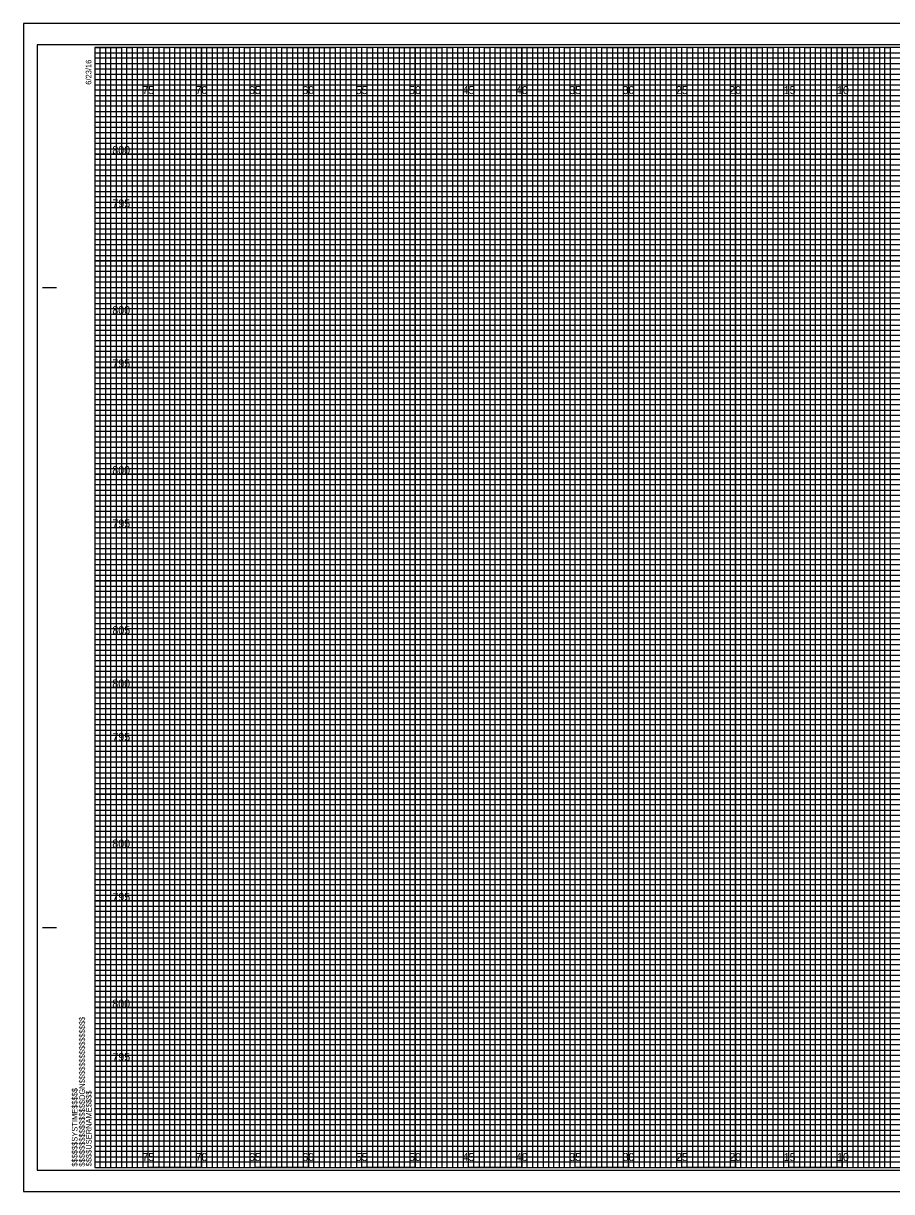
# Model space of a CAD drawing. Extents: x -7 to 162, y -2 to 107.
# Drawn here: x -6.7 to 74.6, y -2.3 to 107.3 of the extents above; entities that cross this region are included whole.
import ezdxf

# ---------------------------------------------------------------- set-up
doc = ezdxf.new("R2010")
doc.units = 0
for name, color, linetype in [('Exist Cross Section Cell', 7, 'Continuous'), ('Exist XS Center Line Elevation Label', 7, 'Continuous'), ('Prop CMT Pvmt Course 2 Wedge', 7, 'Continuous'), ('Prop CMT Shld Paved Course 3', 7, 'Continuous'), ('Prop XS Elevation Labels', 7, 'Continuous'), ('Prop XS Hydro Elevations', 7, 'Continuous'), ('Prop XS SE Text', 7, 'Continuous'), ('Prop XS Side Slope Text', 7, 'Continuous'), ('Sheet Cross Section Grid Minor 2 CELL', 7, 'Continuous'), ('Sheet DOT Grid CELL', 7, 'Continuous'), ('Sheet Plot Border Inside CELL', 7, 'Continuous')]:
    doc.layers.add(name, color=color, linetype=linetype)

msp = doc.modelspace()

# ---------------------------------------------------------------- linework, layer by layer
at = {"layer": 'Exist Cross Section Cell'}
for p, q in [((5, 105), (0, 105)), ((5, 0), (5, 105)), ((15, 105), (10, 105)), ((10, 105), (10, 0)), ((15, 0), (15, 105)), ((25, 105), (20, 105)), ((20, 105), (20, 0)), ((25, 0), (25, 105)), ((35, 105), (30, 105)), ((30, 105), (30, 0)), ((35, 0), (35, 105)), ((45, 105), (40, 105)), ((40, 105), (40, 0)), ((45, 0), (45, 105)), ((55, 105), (50, 105)), ((50, 105), (50, 0)), ((55, 0), (55, 105)), ((65, 105), (60, 105)), ((60, 105), (60, 0)), ((65, 0), (65, 105)), ((75, 105), (70, 105)), ((70, 105), (70, 0)), ((10, 0), (5, 0)), ((20, 0), (15, 0)), ((30, 0), (25, 0)), ((40, 0), (35, 0)), ((50, 0), (45, 0)), ((60, 0), (55, 0)), ((70, 0), (65, 0))]:
    msp.add_line(p, q, dxfattribs=at)
for points in [[(0, 100), (160, 100), (160, 95), (0, 95)], [(0, 90), (160, 90), (160, 85), (0, 85)], [(0, 80), (160, 80), (160, 75), (0, 75)], [(0, 70), (160, 70), (160, 65), (0, 65)], [(0, 60), (160, 60), (160, 55), (0, 55)], [(0, 50), (160, 50), (160, 45), (0, 45)], [(0, 40), (160, 40), (160, 35), (0, 35)], [(0, 30), (160, 30), (160, 25), (0, 25)], [(0, 20), (160, 20), (160, 15), (0, 15)], [(0, 10), (160, 10), (160, 5), (0, 5)]]:
    msp.add_lwpolyline(points, dxfattribs=at)
at = {"layer": 'Exist XS Center Line Elevation Label'}
for points in [[(0, 105), (2.5, 105), (2.5, 0), (7.5, 0), (7.5, 105), (12.5, 105), (12.5, 0), (17.5, 0), (17.5, 105), (22.5, 105), (22.5, 0), (27.5, 0), (27.5, 105), (32.5, 105), (32.5, 0), (37.5, 0), (37.5, 105), (42.5, 105), (42.5, 0), (47.5, 0), (47.5, 105), (52.5, 105), (52.5, 0), (57.5, 0), (57.5, 105), (62.5, 105), (62.5, 0), (67.5, 0), (67.5, 105), (72.5, 105), (72.5, 0), (77.5, 0)], [(0, 102.5), (137.5, 102.5)], [(0, 92.5), (160, 92.5), (160, 97.5), (0, 97.5)], [(0, 82.5), (160, 82.5), (160, 87.5), (0, 87.5)], [(0, 72.5), (160, 72.5), (160, 77.5), (0, 77.5)], [(0, 62.5), (160, 62.5), (160, 67.5), (0, 67.5)], [(0, 52.5), (160, 52.5), (160, 57.5), (0, 57.5)], [(0, 42.5), (160, 42.5), (160, 47.5), (0, 47.5)], [(0, 32.5), (160, 32.5), (160, 37.5), (0, 37.5)], [(0, 22.5), (160, 22.5), (160, 27.5), (0, 27.5)], [(0, 12.5), (160, 12.5), (160, 17.5), (0, 17.5)], [(0, 2.5), (160, 2.5), (160, 7.5), (0, 7.5)]]:
    msp.add_lwpolyline(points, dxfattribs=at)
at = {"layer": 'Prop CMT Pvmt Course 2 Wedge'}
for p, q in [((161.65, 107.25), (-6.7, 107.25)), ((-6.7, 107.25), (-6.7, -2.25)), ((-6.7, -2.25), (161.65, -2.25))]:
    msp.add_line(p, q, dxfattribs=at)
at = {"layer": 'Prop CMT Shld Paved Course 3'}
msp.add_lwpolyline([(-6.7, -2.25), (161.65, -2.25), (161.65, 107.25), (-6.7, 107.25)], close=True, dxfattribs=at)
at = {"layer": 'Prop XS Hydro Elevations'}
for p, q in [((-4.9, 82.5), (-3.65, 82.5)), ((-4.85, 82.5), (-3.6, 82.5)), ((-4.9, 22.5), (-3.65, 22.5)), ((-4.85, 22.5), (-3.6, 22.5)), ((0, 0), (0, 0)), ((0, 0), (0, 0)), ((0, 0), (0, 0)), ((0, 0), (0, 0)), ((0, 0), (0, 0)), ((0, 0), (0, 0)), ((0, 0), (0, 0))]:
    msp.add_line(p, q, dxfattribs=at)
msp.add_lwpolyline([(160, 105), (0, 105), (0, 0), (160, 0)], close=True, dxfattribs=at)
at = {"layer": 'Prop XS Side Slope Text'}
for p, q in [((0, 104.5), (130, 104.5)), ((130, 103.99), (0, 103.99)), ((0, 103.99), (0, 103.5)), ((0, 103.5), (130, 103.5)), ((130, 102.95), (0, 102.95)), ((0, 102.95), (0, 102)), ((0, 102), (160, 102))]:
    msp.add_line(p, q, dxfattribs=at)
for points in [[(0, 101.5), (135, 101.5), (160, 101.5), (160, 101), (0, 101)], [(0, 100.5), (160, 100.5), (160, 99.5), (0, 99.5)], [(0, 99), (160, 99), (160, 98.5), (0, 98.49)], [(0, 98), (160, 98), (160, 97), (0, 97)], [(0, 96.5), (160, 96.5), (160, 96), (0, 96)], [(0, 95.5), (160, 95.5), (160, 94.5), (0, 94.5)], [(0, 94), (160, 94), (160, 93.5), (0, 93.5)], [(0, 93), (160, 93), (160, 92), (0, 92)], [(0, 91.5), (160, 91.5), (160, 91), (0, 91)], [(0, 90.5), (160, 90.5), (160, 89.5), (0, 89.5)], [(0, 89), (160, 89), (160, 88.5), (0, 88.5)], [(0, 88), (160, 88), (160, 86.98), (160, 86.5), (160, 86), (0, 86)], [(0, 87), (160, 87), (160, 86.5), (0, 86.5)], [(0, 85.5), (160, 85.5), (160, 84.5), (0, 84.52)], [(0, 84.52), (160, 84.5), (160, 84), (0, 84)], [(0, 83.5), (160, 83.5), (160, 83), (0, 83)], [(0, 82), (160, 82), (160, 81.5), (0, 81.5)], [(0, 81), (160, 81), (160, 80.5), (0, 80.5)], [(-0.04, 79.45), (160, 79.45), (160, 78.94), (-0.04, 78.94)], [(0, 78.5), (160, 78.5), (160, 78), (0, 78)], [(0, 77), (160, 77), (160, 76.5), (0, 76.5)], [(0, 76), (160, 76), (160, 75.5), (0, 75.5)], [(0, 74.5), (160, 74.5), (160, 74), (0, 74)], [(0, 73.5), (160, 73.5), (160, 73), (0, 73)], [(0, 72), (160, 72), (160, 71.5), (0, 71.5)], [(0, 71), (160, 71), (160, 70.5), (0, 70.5)], [(0, 69.5), (160, 69.5), (160, 68.99), (0, 69)], [(0, 68.5), (160, 68.5), (160, 68), (0, 68)], [(0, 67), (160, 67), (160, 66.5), (0, 66.5)], [(0, 66), (160, 66), (160, 65.5), (0, 65.5)], [(0, 64.5), (160, 64.5), (160, 64), (0, 64)], [(0, 63.5), (160, 63.5), (160, 63), (0, 63)], [(0, 62), (160, 62), (160, 61.5), (0, 61.5)], [(0, 61), (160, 61), (160, 60.5), (0, 60.5)], [(0, 59.5), (160, 59.5), (160, 59), (0, 59)], [(0, 58.5), (160.03, 58.45), (160, 58), (0, 58)], [(0, 57), (160, 57), (160, 56.5), (0, 56.5)], [(0, 56), (160, 56), (160, 55.5), (0, 55.5)], [(0, 54.5), (160, 54.5), (160, 54), (0, 54)], [(0, 53.5), (160, 53.5), (160, 53), (0, 53)], [(0, 52), (160, 52), (160, 51.5), (0, 51.5)], [(0, 51), (160, 51), (160, 50.5), (0, 50.5)], [(0, 49.5), (160, 49.5), (160, 49), (0, 49)], [(0, 48.5), (160, 48.5), (160, 48), (0, 48)], [(0, 47), (160, 47), (160, 46.5), (0, 46.5)], [(0, 46), (160, 46), (160, 45.5), (0, 45.5)], [(0, 44.5), (160, 44.5), (160, 44), (0, 44)], [(0, 43.5), (160, 43.5), (160, 43), (0, 43)], [(0, 42), (160, 42), (160, 41.5), (0, 41.5)], [(0, 41), (160, 41), (160, 40.5), (0, 40.5)], [(0, 39.5), (160, 39.5), (160, 38.99), (0, 39)], [(0, 38.5), (160, 38.5), (160, 38), (0, 38)], [(0, 37), (160, 37), (160, 36.5), (0, 36.5)], [(0, 36), (160, 36), (160, 35.5), (0, 35.5)], [(0, 34.5), (160, 34.5), (160, 34), (0, 34)], [(0, 33.5), (160, 33.5), (160, 33), (0, 33)], [(0, 32), (160, 32), (160, 31.5), (0, 31.5)], [(0, 31), (160, 31), (160, 30.5), (0, 30.5)], [(0, 29.5), (160, 29.5), (160, 29), (0, 29)], [(0, 28.5), (160.03, 28.46), (160, 28), (0, 28)], [(0, 27), (160, 27), (160, 26.5), (0, 26.5)], [(0, 26), (160, 26), (160, 25.5), (0, 25.5)], [(0, 24.5), (160, 24.5), (160, 24), (0, 24)], [(0, 23.5), (160, 23.5), (160, 23), (0, 23)], [(0, 22), (160, 22), (160, 21.5), (0, 21.5)], [(0, 21), (160, 21), (160, 20.5), (0, 20.5)], [(0, 19.5), (160, 19.5), (160, 19), (0, 19)], [(0, 18.5), (160, 18.5), (160, 18), (0, 18)], [(0, 17), (160, 17), (160, 16.5), (0, 16.5)], [(0, 16), (160, 16), (160, 15.5), (0, 15.5)], [(0, 14.5), (160, 14.5), (160, 14), (0, 14)], [(0, 13.5), (160, 13.5), (160, 13), (0, 13)], [(0, 12), (160, 12), (160, 11.5), (0, 11.5)], [(0, 11), (160, 11), (160, 10.5), (0, 10.5)], [(0, 9.5), (160, 9.5), (160, 9), (0, 9)], [(0, 8.5), (160, 8.5), (160, 8), (0, 8)], [(0, 7), (160, 7), (160, 6.5), (0, 6.5)], [(0, 6), (160, 6), (160, 5.5), (0, 5.5)], [(0, 4.5), (160, 4.5), (160, 4), (0, 4)], [(0, 3.5), (160, 3.5), (160, 3), (0, 3)], [(0, 2), (160, 2), (160, 1.5), (0, 1.5)], [(0, 1), (160, 1), (160, 0.5), (0, 0.5)]]:
    msp.add_lwpolyline(points, dxfattribs=at)
at = {"layer": 'Sheet Cross Section Grid Minor 2 CELL'}
for points in [[(0, 0), (0.5, 0), (0.5, 105), (1, 105), (1, 0)], [(1, 0), (1.5, 0), (1.5, 105), (2, 105), (2, 0)], [(2.5, 0), (3, 0), (3, 105), (3.5, 105), (3.5, 0)], [(3.5, 0), (4, 0), (4, 105), (4.5, 105), (4.5, 0)], [(5, 0), (5.5, 0), (5.5, 105), (6, 105), (6, 0)], [(6, 0), (6.5, 0), (6.5, 105), (7, 105), (7, 0)], [(7.5, 0), (8, 0), (8, 105), (8.5, 105), (8.5, 0)], [(8.5, 0), (9, 0), (9, 105), (9.5, 105), (9.5, 0)], [(10, 0), (10.5, 0), (10.5, 105), (11, 105), (11, 0)], [(11, 0), (11.5, 0), (11.5, 105), (12, 105), (12, 0)], [(12.5, 0), (13, 0), (13, 105), (13.5, 105), (13.5, 0)], [(13.5, 0), (14, 0), (14, 105), (14.5, 105), (14.5, 0)], [(15, 0), (15.5, 0), (15.5, 105), (16, 105), (16, 0)], [(16, 0), (16.5, 0), (16.5, 105), (17, 105), (17, 0)], [(17.5, 0), (18, 0), (18, 105), (18.5, 105), (18.5, 0)], [(18.5, 0), (19, 0), (19, 105), (19.5, 105), (19.5, 0)], [(20, 0), (20.5, 0), (20.5, 105), (21, 105), (21, 0)], [(21, 0), (21.5, 0), (21.5, 105), (22, 105), (22, 0)], [(22.5, 0), (23, 0), (23, 105), (23.5, 105), (23.5, 0)], [(23.5, 0), (24, 0), (24, 105), (24.5, 105), (24.5, 0)], [(25, 0), (25.5, 0), (25.5, 105), (26, 105), (26, 0)], [(26, 0), (26.5, 0), (26.5, 105), (27, 105), (27, 0)], [(27.5, 0), (28, 0), (28, 105), (28.5, 105), (28.5, 0)], [(28.5, 0), (29, 0), (29, 105), (29.5, 105), (29.5, 0)], [(30, 0), (30.5, 0), (30.5, 105), (31, 105), (31, 0)], [(31, 0), (31.5, 0), (31.5, 105), (32, 105), (32, 0)], [(32.5, 0), (33, 0), (33, 105), (33.5, 105), (33.5, 0)], [(33.5, 0), (34, 0), (34, 105), (34.5, 105), (34.5, 0)], [(35, 0), (35.5, 0), (35.5, 105), (36, 105), (36, 0)], [(36, 0), (36.5, 0), (36.5, 105), (37, 105), (37, 0)], [(37.5, 0), (38, 0), (38, 105), (38.5, 105), (38.5, 0)], [(38.5, 0), (39, 0), (39, 105), (39.5, 105), (39.5, 0)], [(40, 0), (40.5, 0), (40.5, 105), (41, 105), (41, 0)], [(41, 0), (41.5, 0), (41.5, 105), (42, 105), (42, 0)], [(42.5, 0), (43, 0), (43, 105), (43.5, 105), (43.5, 0)], [(43.5, 0), (44, 0), (44, 105), (44.5, 105), (44.5, 0)], [(45, 0), (45.5, 0), (45.5, 105), (46, 105), (46, 0)], [(46, 0), (46.5, 0), (46.5, 105), (47, 105), (47, 0)], [(47.5, 0), (48, 0), (48, 105), (48.5, 105), (48.5, 0)], [(48.5, 0), (49, 0), (49, 105), (49.5, 105), (49.5, 0)], [(50, 0), (50.5, 0), (50.5, 105), (51, 105), (51, 0)], [(51, 0), (51.5, 0), (51.5, 105), (52, 105), (52, 0)], [(52.5, 0), (53, 0), (53, 105), (53.5, 105), (53.5, 0)], [(53.5, 0), (54, 0), (54, 105), (54.5, 105), (54.5, 0)], [(55, 0), (55.5, 0), (55.5, 105), (56, 105), (56, 0)], [(56, 0), (56.5, 0), (56.5, 105), (57, 105), (57, 0)], [(57.5, 0), (58, 0), (58, 105), (58.5, 105), (58.5, 0)], [(58.5, 0), (59, 0), (59, 105), (59.5, 105), (59.5, 0)], [(60, 0), (60.5, 0), (60.5, 105), (61, 105), (61, 0)], [(61, 0), (61.5, 0), (61.5, 105), (62, 105), (62, 0)], [(62.5, 0), (63, 0), (63, 105), (63.5, 105), (63.5, 0)], [(63.5, 0), (64, 0), (64, 105), (64.5, 105), (64.5, 0)], [(65, 0), (65.5, 0), (65.5, 105), (66, 105), (66, 0)], [(66, 0), (66.5, 0), (66.5, 105), (67, 105), (67, 0)], [(67.5, 0), (68, 0), (68, 105), (68.5, 105), (68.5, 0)], [(68.5, 0), (69, 0), (69, 105), (69.5, 105), (69.5, 0)], [(70, 0), (70.5, 0), (70.5, 105), (71, 105), (71, 0)], [(71, 0), (71.5, 0), (71.5, 105), (72, 105), (72, 0)], [(72.5, 0), (73, 0), (73, 105), (73.5, 105), (73.5, 0)], [(73.5, 0), (74, 0), (74, 105), (74.5, 105), (74.5, 0)]]:
    msp.add_lwpolyline(points, dxfattribs=at)
at = {"layer": 'Sheet DOT Grid CELL'}
for p, q in [((5, 0), (5, 105)), ((10, 0), (10, 105)), ((15, 0), (15, 105)), ((20, 0), (20, 105)), ((25, 0), (25, 105)), ((30, 0), (30, 105)), ((35, 0), (35, 105)), ((40, 0), (40, 105)), ((45, 0), (45, 105)), ((50, 0), (50, 105)), ((55, 0), (55, 105)), ((60, 0), (60, 105)), ((65, 0), (65, 105)), ((70, 0), (70, 105)), ((0, 100), (160, 100)), ((0, 95), (160, 95)), ((0, 90), (160, 90)), ((0, 85), (160, 85)), ((0, 80), (160, 80)), ((0, 75), (160, 75)), ((0, 70), (160, 70)), ((0, 65), (160, 65)), ((0, 60), (160, 60)), ((0, 55), (160, 55)), ((0, 50), (160, 50)), ((0, 45), (160, 45)), ((0, 40), (160, 40)), ((0, 35), (160, 35)), ((0, 30), (160, 30)), ((0, 25), (160, 25)), ((0, 20), (160, 20)), ((0, 15), (160, 15)), ((0, 10), (160, 10)), ((0, 5), (160, 5))]:
    msp.add_line(p, q, dxfattribs=at)
at = {"layer": 'Sheet Plot Border Inside CELL'}
msp.add_lwpolyline([(-5.4, -0.25), (161.2, -0.25), (161.2, 105.25), (-5.4, 105.25)], close=True, dxfattribs=at)

# ---------------------------------------------------------------- texts
at = {"layer": 'Prop XS Elevation Labels'}
for s, p in [('800', (1.63, 95)), ('795', (1.64, 90)), ('800', (1.63, 80)), ('795', (1.64, 75)), ('800', (1.63, 65)), ('795', (1.64, 60)), ('805', (1.64, 50)), ('800', (1.63, 45)), ('795', (1.64, 40)), ('800', (1.63, 30)), ('795', (1.64, 25)), ('800', (1.63, 15)), ('795', (1.64, 10))]:
    msp.add_text(s, height=0.75, dxfattribs=at).set_placement(p)
at = {"layer": 'Prop XS Hydro Elevations'}
for s, p in [('6/23/16', (-0.33, 101.5)), ('$$$$$$$$$$$$$$$$DGN$$$$$$$$$$$$$$$$', (-0.94, 0.09)), ('$$$$$$SYSTIME$$$$$', (-1.63, 0.09)), ('$$$$USERNAME$$$$', (-0.31, 0.12))]:
    msp.add_text(s, height=0.525, rotation=90, dxfattribs=at).set_placement(p)
at = {"layer": 'Prop XS SE Text'}
for s, p in [('75', (4.44, 100.62)), ('70', (9.43, 100.62)), ('65', (14.44, 100.62)), ('60', (19.43, 100.62)), ('55', (24.44, 100.62)), ('50', (29.43, 100.62)), ('45', (34.44, 100.62)), ('40', (39.43, 100.62)), ('35', (44.44, 100.62)), ('30', (49.43, 100.62)), ('25', (54.44, 100.62)), ('20', (59.43, 100.62)), ('15', (64.53, 100.62)), ('10', (69.52, 100.62)), ('75', (4.44, 0.62)), ('70', (9.43, 0.62)), ('65', (14.44, 0.62)), ('60', (19.43, 0.62)), ('55', (24.44, 0.62)), ('50', (29.43, 0.62)), ('45', (34.44, 0.62)), ('40', (39.43, 0.62)), ('35', (44.44, 0.62)), ('30', (49.43, 0.62)), ('25', (54.44, 0.62)), ('20', (59.43, 0.62)), ('15', (64.53, 0.62)), ('10', (69.52, 0.62))]:
    msp.add_text(s, height=0.75, dxfattribs=at).set_placement(p)

doc.saveas('drawing.dxf')
